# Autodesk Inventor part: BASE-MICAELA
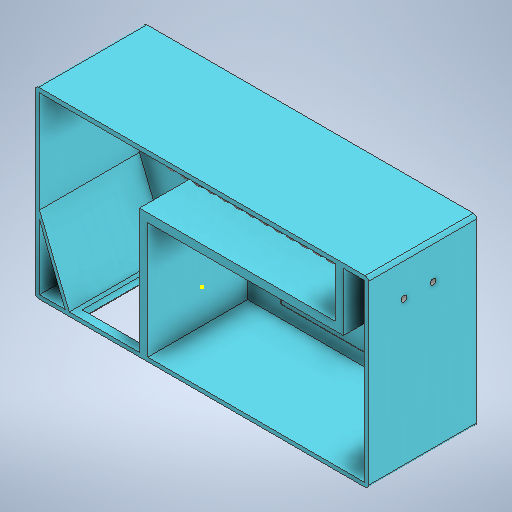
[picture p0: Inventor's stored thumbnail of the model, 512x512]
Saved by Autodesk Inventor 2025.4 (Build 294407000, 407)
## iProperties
Created: 2026-06
Part Number: BASE-MICAELA
Material: Generic
Document SubType Name: Modeling
Designer: Marcio Valenzuela
Density: 1 g/cm^3
Appearance: Default
Author: Marcio Valenzuela
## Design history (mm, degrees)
sketch "Sketch1"
  geometry: L1 (-200, 110.247)-(200, 110.247); L2 (200, 110.247)-(200, -109.753); L3 (200, -109.753)-(-200, -109.753); L4 (-200, -109.753)-(-200, 110.247); L5 (-200, 110.247)-(200, -109.753); L6 (200, 110.247)-(-200, -109.753); 2 further points
  constraints: 12 end point, 2 midpoint, 2 parallel, 1 horizontal, 1 perpendicular
  dimensions: "d0" = 400 distance of L2.end L3.end; "d1" = 220 distance of L1.end L2.end
extrude "Extrusion1" new body sketch "Sketch1" distance "d2" = 130; taper "d3" = 0 deg
sketch "Sketch2"
  geometry: L1 (-195, 105)-(195, 105); L2 (195, 105)-(195, -105); L3 (195, -105)-(-195, -105); L4 (-195, -105)-(-195, 105); L5 (-195, 105)-(195, -105); L6 (195, 105)-(-195, -105); 1 further point
  constraints: 12 end point, 2 midpoint, 2 parallel, 1 horizontal, 1 perpendicular
  dimensions: "d4" = 390 distance of L2.end L3.end; "d5" = 210 distance of L1.end L2.end
extrude "Extrusion2" cut sketch "Sketch2" distance "d6" = 120; taper "d7" = 0 deg
sketch "Sketch3"
  geometry: L1 (-75, -105)-(-65, -105); L2 (-65, 35)-(170, 35); L3 (160, 45)-(-75, 45); L4 (-65, -105)-(-65, 35); L5 (-75, -105)-(-75, 45); L6 (170, 35)-(170, 105); L7 (-195, 105)-(195, 105) reference; L8 (160, 45)-(160, 105); L9 (160, 105)-(170, 105); 3 further points
  constraints: 16 end point, 3 vertical, 2 point on line, 1 parallel, 1 perpendicular
  dimensions: "d12" = 10 distance of L1.start L1.end; "d26" = 140 distance of L1.end L4.end; "d27" = 150 distance of L1.start L5.end
extrude "Extrusion3" join sketch "Sketch3" distance "d18" = 120; taper "d19" = 0 deg
sketch "Sketch4"
  geometry: L1 (-195, -17)-(-159.209, -105); L2 (-159.209, -105)-(-169.209, -105); L3 (-195, -17)-(-195, -27); L4 (-195, -27)-(-164.209, -105); L5 (-164.209, -105)-(-159.209, -105); 2 further points
  constraints: 10 end point, 1 collinear, 1 midpoint
  dimensions: "d20" = 88 distance of point (-195, -105) L1.start; "d21" = 95 distance of L1.start L1.end; "d22" = 10 distance of L1.end L2.end; "d23" = 10 distance of L1.start L3.end
extrude "Extrusion4" join sketch "Sketch4" distance "d24" = 120; taper "d25" = 0 deg
sketch "Sketch5"
  geometry: L1 (50.396, 120)-(115.396, 120); L2 (115.396, 120)-(115.396, 20); L3 (115.396, 20)-(50.396, 20); L4 (50.396, 20)-(50.396, 120); L5 (50.396, 120)-(115.396, 20); L6 (115.396, 120)-(50.396, 20); 2 further points
  constraints: 12 end point, 2 parallel, 1 horizontal, 1 perpendicular
  dimensions: "d28" = 65 distance of L2.end L3.end; "d29" = 100 distance of L1.end L2.end
extrude "Extrusion5" cut sketch "Sketch5" distance "d30" = 120; taper "d31" = 0 deg
chamfer "Chamfer1" distance "d32" = 4; stored, may be unused: second distance "d33" = 2, angle "d34" = 45 deg
workplane "Work Plane1"
sketch "Sketch10"
  geometry: L1 (0, 0)-(0, 60) reference; L2 (120, 60)-(120, -150) reference; C1 r 20 at (60, 30); 1 further point
  constraints: 1 centre point
  dimensions: "d61" = 40 diameter of C1
extrude "Extrusion8" join sketch "Sketch10" distance "d62" = 1; taper "d63" = 0 deg
workplane "Work Plane3"
sketch "Sketch11"
  geometry: C1 r 3 at (160, 55); 1 further point
  constraints: 1 centre point, 1 coincident
  dimensions: "d71" = 6 diameter of C1
workaxis "Work Axis2"
sketch "Sketch12"
  geometry: L1 (160, 55)-(160, 95) reference; C1 r 3 at (160, 55); 1 further point
  constraints: 1 centre point
  dimensions: "d80" = 6 diameter of C1
coil "Coil3" sketch "Sketch12" pitch "d81" = 16; turns "d83" = 16; dims "d82" = 20, "d84" = 0, angle "d85" = 90 deg, angle "d86" = 90 deg, "d87" = 0, "d88" = 0
sketch "Sketch13"
  geometry: C1 r 23 at (60, 30); A1 r 20 centre (60, 30) between (80, 30) and (60, 10) reference; 2 further points
  constraints: 1 centre point, 1 coincident
  dimensions: "d89" = 46 diameter of C1
extrude "Extrusion9" join sketch "Sketch13" distance "d90" = 2; taper "d91" = 0 deg
fillet "Fillet1" dims "d92" = 4
sketch "Sketch14"
  geometry: L1 (-60, 40)-(-60, 32); C1 r 4.5 at (-60, 40); C2 r 1.8 at (-77.5, 32); C3 r 1.8 at (-42.5, 32); 2 further points
  constraints: 3 centre point, 2 end point, 1 coincident, 1 vertical
  dimensions: "d93" = 9 diameter of C1; "d96" = 3.6 diameter of C2; "d97" = 3.6 diameter of C3; "d98" = 8 distance of L1.start L1.end
extrude "Extrusion10" cut sketch "Sketch14" distance "d99" = 1.5; taper "d100" = 0 deg
sketch "Sketch15"
  geometry: L1 (-1.5, 2)-(1.5, 2); L2 (1.5, -2)-(-1.5, -2); A1 r 2.5 centre (0, 0) between (-1.5, 2) and (-1.5, -2); A2 r 2.5 centre (0, 0) between (1.5, -2) and (1.5, 2); 2 further points
  constraints: 4 end point, 4 point on circle, 2 centre point, 1 coincident, 1 horizontal, 1 parallel
extrude "Extrusion11" cut sketch "Sketch15" distance "d102" = 8.5; taper "d103" = 0 deg
sketch "Sketch16"
  geometry: L1 (195, 105)-(195, -105) reference; L2 (-25, 20)-(155, 20); L3 (155, 20)-(155, -90); L4 (155, -90)-(-25, -90); L5 (-25, -90)-(-25, 20); L6 (-25, 20)-(155, -90); L7 (155, 20)-(-25, -90)
  constraints: 12 end point, 2 parallel, 1 horizontal, 1 perpendicular
  dimensions: "d107" = 180 distance of L3.end L4.end; "d108" = 110 distance of L2.end L3.end
extrude "Extrusion12" cut sketch "Sketch16" distance "d109" = 0.5; taper "d110" = 0 deg
sketch "Sketch17"
  geometry: C1 r 3.5 at (-87.5, 172.753); C2 r 3.5 at (-52.5, 172.753); 3 further points
  constraints: 2 centre point, 2 coincident
  dimensions: "d112" = 7 diameter of C2
extrude "Extrusion13" cut sketch "Sketch17" distance "d113" = 10; taper "d114" = 0 deg
sketch "Sketch18"
  geometry: 1 further point
body "Solid1"
